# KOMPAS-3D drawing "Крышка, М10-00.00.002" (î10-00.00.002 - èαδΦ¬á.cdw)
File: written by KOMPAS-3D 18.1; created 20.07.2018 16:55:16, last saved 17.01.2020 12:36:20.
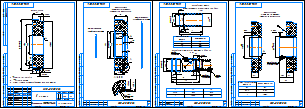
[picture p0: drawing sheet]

Sheets 1-4: A4, portrait

Document properties: Масса: 0.324102; Форматы листов документа: 4xA4

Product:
- Part/product: Крышка  | designation М10-00.00.002
    Материал: Полипропилен  ГОСТ 26996-86 (density 900 kg/m3)
    Масса: 0.324102
    Раздел спецификации: Детали
    Форматы листов документа: 2xA4, A3
    Примечание: @100~)2xA4, A3
    source file: М10-00.00.002 - Крышка.cdw
- Part/product: Крышка ПВХ  | designation М13-01.00.002
    Материал: Полипропилен  ГОСТ 26996-86 (density 900 kg/m3)
    Масса: 0.324102
    Раздел спецификации: Детали
    Форматы листов документа: 2xA4См. заказ
    Примечание: @100~)2xA4См. заказ
- Part/product: Крышка  | designation М10-00.00.002-01
    Материал: Полипропилен  ГОСТ 26996-86 (density 900 kg/m3)
    Масса: 0.345988
    Раздел спецификации: Детали
    Форматы листов документа: 2xA4
    Примечание: @100~)2xA4
    source file: М10-00.00.002 - Крышка.cdw

Title block, sheet 1: Наименование: Крышка; designation: М10-00.00.002; Материал: Полипропилен  ГОСТ 26996-86; Масса: 0,32; scale: 1:1; sheet number: 1; Количество листов документа: 4; organisation: АО «Астерион»; Форматы листов документа: A4; stored path: Z:\Магна\Магна Ins\Магна ins 10\М10-00.00.000\3Д\М10-00.00.002 - Крышка.cdw; Разработал: Милов; Т. контр.: Лучихин
Title block, sheet 2: sheet number: 2
Title block, sheet 3: sheet number: 3; stored path: D:\Magna\Магна Ins\Магна ins 10\М10-00.00.000\3Д\М10-00.00.002 - Крышка.cdw
Title block, sheet 4: sheet number: 4

Views: Вид 1, Местный разрез 1, Спереди, Проекционный вид 2, Вид 3, Выносной элемент 4, Проекционный вид 6, Вид 9, Проекционный вид 11, Вид 12, Выносной элемент А, Выносной элемент
Referenced files in Z:\Магна\Магна Ins\Магна ins 10\М10-00.00.000\3Д\: М10-00.00.002 - Крышка.m3d
Referenced files in D:\Magna\Магна Ins\Магна ins 10\М10-00.00.000\3Д\: М10-00.00.002 - Крышка.m3d, Труба 63 для крышки с фильтром.m3d, Фильтр РР2700.m3d, Труба 1165 для фильтра.a3d
Referenced files in D:\Magna\Магна Ins\Магна ins 11\Магна N\3Д\Магна INS 11\: Всасывающая трубка 75.m3d
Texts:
  Крышка М10 для фильтра
  Остальное см.  М10-00.00.002
  Труба 63 PN10 S=5,8
  FV PPR ф. FV PLAST
  Крышка М10 для патрубка
  max**
  + Кольцо 125-130-30
  ГОСТ 9833-73 Viton 1 шт.
  Длина всасывающей
  трубы (L)
  Длина трубы (L1)
  Всасывающая труба
  Материал Труба полипропилен  75 PN16
  + Кольцо 058-064-36
  Всасывающая труба для фильтра 1" PP2700
  Труба 75 PN16
  Фильтр 1"
  PP2700
  Сборка
  Лифлянд
  Труба 63 для крышки с фильтром
  Фильтр РР2700
Dimensions and other numbers on the sheet: 10; 8; 4 отв.; 115; 140; 2,5; 131; 0,5; 29; 1; 54; 5; 62; 20; 4; 52; 37; 17; 60; 35; 76; 75; 26; 64; 2,6; 0,1; 0,4; 6,4; 125,3; 129,7; 2; 0,2; 100; 126; 200; 226; 57,8; 69; 3; 1165; 1131; 1114; 60х3-7Н; 1:1; 0,32; 28.10.2019; 11.11.2019; 01

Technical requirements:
  *Размеры для справок
  **Обеспеч. инстр.
  Общие допуски ГОСТ 30893.2-mK (H14, h14,  t2/2).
